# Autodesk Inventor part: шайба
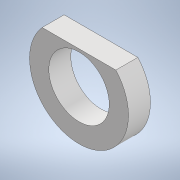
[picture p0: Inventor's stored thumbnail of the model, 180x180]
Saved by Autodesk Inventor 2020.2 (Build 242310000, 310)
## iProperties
Created: 2020-04
Part Number: шайба
Material: Типовые
Document SubType Name: Modeling
Designer: Алексей
Density: 1 g/cm^3
Appearance: По умолчанию
Author: Алексей
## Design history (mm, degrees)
sketch "Эскиз1"
  geometry: L1 (-7, -2)-(7, -2) reference; C1 r 2.75 at (0, -5) reference; C2 r 4.5 at (0, -5); 3 further points
  constraints: 1 centre point, 1 coincident
  dimensions: "d0" = 9 diameter of C2
extrude "Выдавливание1" new body sketch "Эскиз1" distance "d1" = 2; taper "d2" = 0 deg
node "Твердое тело1"
node "Ссылка1"
node "Ссылка2"
feature "Машинка.iam"
